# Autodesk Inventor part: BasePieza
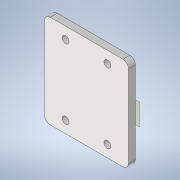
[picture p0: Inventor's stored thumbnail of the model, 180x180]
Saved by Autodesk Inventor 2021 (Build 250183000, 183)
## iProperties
Created: 2021-02
Part Number: BasePieza
Material: Genérico
Document SubType Name: Modeling
Designer: ATOUZA
Density: 1 g/cm^3
Appearance: Valor por defecto
Author: ATOUZA
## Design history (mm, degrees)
node "Plano de trabajo1"
sketch "Boceto1"
  geometry: L1 (0, -26.365)-(0, -13.632) reference; L2 (0, -13.632)-(-60, -13.632) reference; L3 (-60, -26.365)-(-60, -13.632) reference; L4 (0, -26.365)-(-60, -26.365) reference; L5 (0, 27.632)-(0, 40.365) reference; L6 (0, 40.365)-(-60, 40.365) reference; L7 (-60, 27.632)-(-60, 40.365) reference; L8 (0, 27.632)-(-60, 27.632) reference; L9 (-60, -26.365)-(0, -26.365); L10 (0, -26.365)-(0, 40.365); L11 (0, 40.365)-(-60, 40.365); L12 (-60, 40.365)-(-60, -26.365); L13 (-60, 7)-(0, 7); L14 (-30, 40.365)-(-30, -26.365); C1 r 2.5 at (-45, -18) reference; C2 r 2.5 at (-15, -18) reference; C3 r 2.5 at (-45, 32) reference; C4 r 2.5 at (-15, 32) reference; C5 r 2.5 at (-45, -18); C6 r 2.5 at (-15, -18); C7 r 2.5 at (-45, 32); C8 r 2.5 at (-15, 32); 1 further point
  constraints: 12 end point, 4 centre point, 4 coincident, 4 concentric, 4 midpoint, 2 parallel, 1 horizontal, 1 perpendicular
extrude "Extrusión1" new body sketch "Boceto1" distance "d0" = 5; taper "d1" = 0 deg
fillet "Empalme1" dims "d2" = 4
node "Sólido1"
node "Referencia1"
node "Referencia2"
